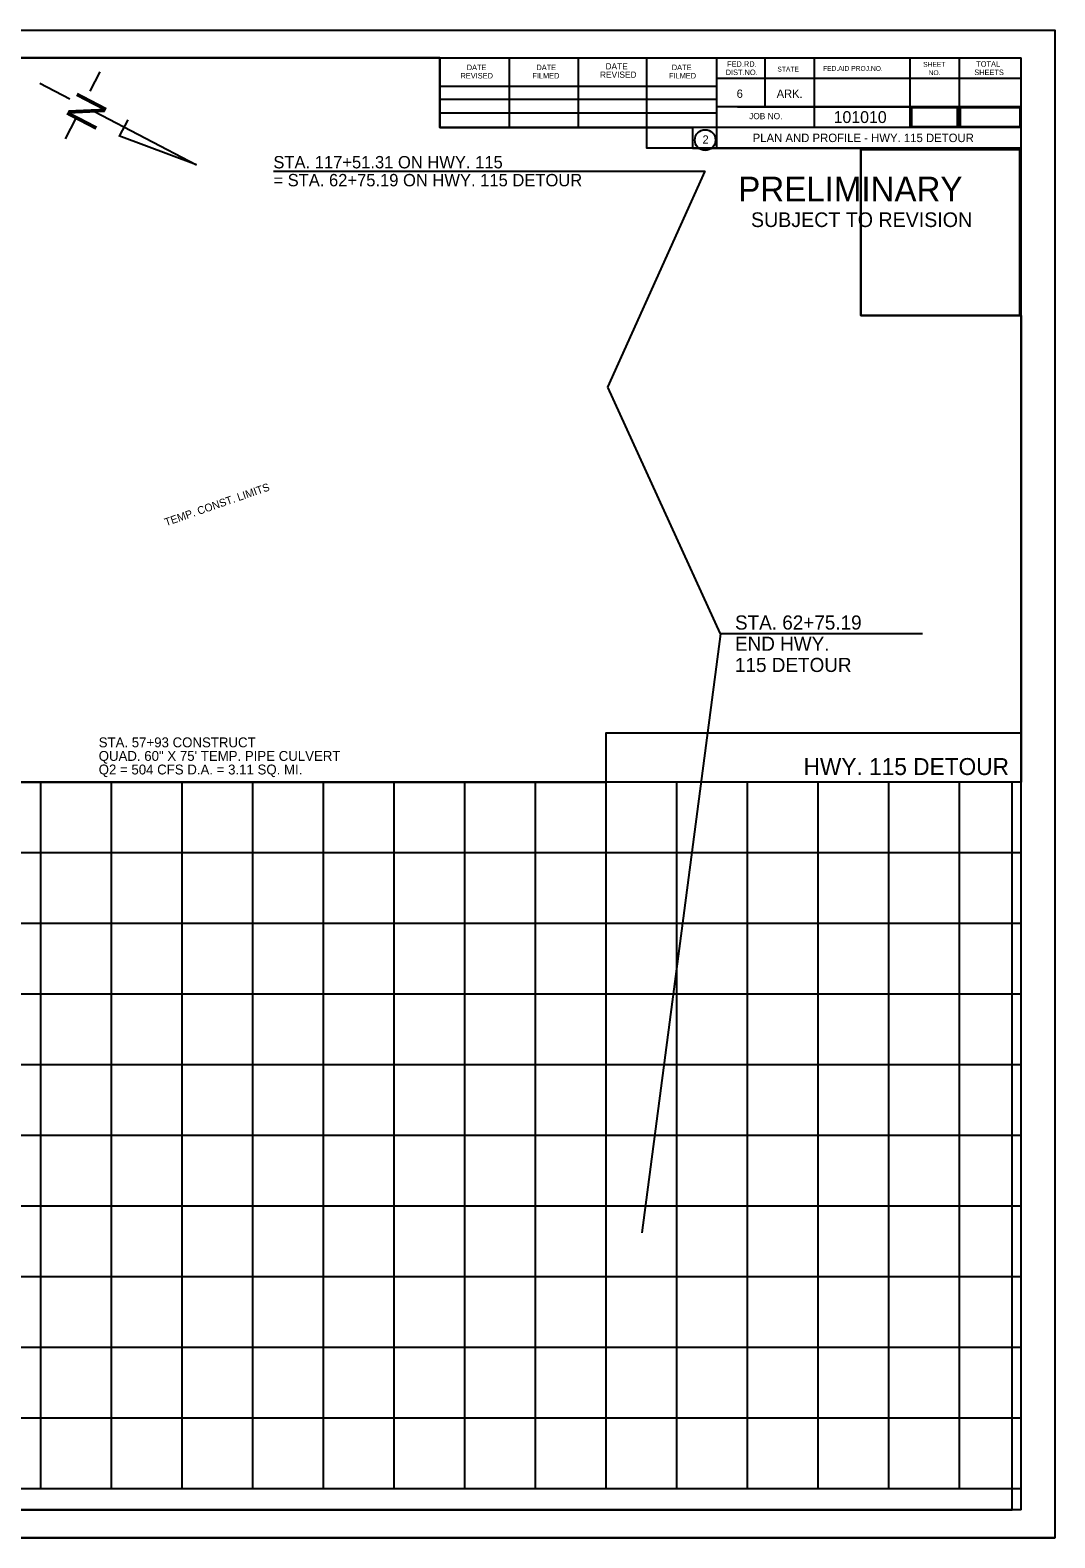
# Model space of a CAD drawing. Extents: x 9887 to 11605, y 9980 to 11268.
# Drawn here: x 10880 to 11605, y 9980 to 11047 of the extents above; entities that cross this region are included whole.
import ezdxf

# ---------------------------------------------------------------- set-up
doc = ezdxf.new("R2010")
doc.units = 0
for name, color, linetype in [('DATE', 7, 'Continuous'), ('GREEN_TXT', 7, 'Continuous'), ('Page Number', 7, 'Continuous'), ('R_Alg Annot', 7, 'Continuous'), ('R_Border Notes', 7, 'Continuous'), ('R_Border PE', 7, 'Continuous'), ('R_No Plot', 7, 'Continuous'), ('R_Proposed Const Limits Annot', 7, 'Continuous'), ('RC Box Annot', 7, 'Continuous'), ('SEAL-INFO', 7, 'Continuous'), ('SIGNATURE', 7, 'Continuous'), ('Total_Pages', 7, 'Continuous')]:
    doc.layers.add(name, color=color, linetype=linetype)

msp = doc.modelspace()

# ---------------------------------------------------------------- linework, layer by layer
for p, q in [((10886.6, 11009.4), (10907.8, 10998.3)), ((10929.1, 11017.4), (10922, 11003.7)), ((10925.3, 10989.2), (10997.4, 10951.6)), ((10912, 10984.5), (10904.4, 10969.9)), ((10948.8, 10983.3), (10942.8, 10971.8)), ((10997.4, 10951.6), (10942.4, 10972))]:
    msp.add_line(p, q)
at = {"layer": 'DATE'}
msp.add_line((11368.1, 10619.6), (11312.5, 10195.9), dxfattribs=at)
msp.add_lwpolyline([(11511.1, 10619.6), (11368.1, 10619.6), (11288.4, 10794.3)], dxfattribs=at)
at = {"layer": 'GREEN_TXT'}
for p, q in [((10000, 11027.3), (11580.9, 11027.3)), ((11169.6, 10977.9), (11169.6, 11027.3)), ((11218.9, 10977.9), (11218.9, 11026.3)), ((11267.7, 10977.9), (11267.7, 11026.3)), ((11316.1, 10977.9), (11316.1, 11026.3)), ((11365.4, 11027.3), (11365.4, 10963.3)), ((11399.6, 11027.3), (11399.6, 10992.6)), ((11434.3, 11027.3), (11434.3, 10977.9)), ((11502.2, 11027.3), (11502.2, 10977.9)), ((11536.9, 11027.3), (11536.9, 10977.9)), ((11580.9, 10000), (11580.9, 11027.3)), ((11580.9, 11012.6), (11365.4, 11012.6)), ((11580.9, 11012.7), (11580.9, 11012.7)), ((11169.6, 11007.2), (11365.4, 11007.2)), ((11169.6, 10997.9), (11365.4, 10997.9)), ((11169.6, 10977.9), (11169.6, 10988.2)), ((11169.6, 10988.2), (11365.4, 10988.2)), ((11580.9, 10992.6), (11365.4, 10992.6)), ((11380.2, 10992.6), (11580.9, 10992.6)), ((11580.9, 10977.9), (11169.6, 10977.9)), ((11365.4, 10963.3), (11580.9, 10963.3)), ((11580.9, 10514.7), (10000, 10514.7)), ((10887.3, 10014.7), (10887.3, 10514.7)), ((10937.3, 10014.7), (10937.3, 10514.7)), ((10987.3, 10014.7), (10987.3, 10514.7)), ((11037.3, 10014.7), (11037.3, 10514.7)), ((11087.3, 10014.7), (11087.3, 10514.7)), ((11137.3, 10014.7), (11137.3, 10514.7)), ((11187.3, 10014.7), (11187.3, 10514.7)), ((11237.3, 10014.7), (11237.3, 10514.7)), ((11287.3, 10014.7), (11287.3, 10514.7)), ((11337.3, 10014.7), (11337.3, 10514.7)), ((11387.3, 10014.7), (11387.3, 10514.7)), ((11437.3, 10014.7), (11437.3, 10514.7)), ((11487.3, 10014.7), (11487.3, 10514.7)), ((11537.3, 10014.7), (11537.3, 10514.7)), ((11580.9, 10464.7), (10000, 10464.7)), ((11580.9, 10414.7), (10000, 10414.7)), ((11580.9, 10364.7), (10000, 10364.7)), ((11580.9, 10314.7), (10000, 10314.7)), ((11580.9, 10264.7), (10000, 10264.7)), ((11580.9, 10214.7), (10000, 10214.7)), ((11580.9, 10164.7), (10000, 10164.7)), ((11580.9, 10114.7), (10000, 10114.7)), ((11580.9, 10064.7), (10000, 10064.7)), ((11580.9, 10014.7), (10000, 10014.7)), ((11580.9, 10000), (10000, 10000))]:
    msp.add_line(p, q, dxfattribs=at)
msp.add_circle((11357.3, 10969), 7.33, dxfattribs=at)
at = {"layer": 'Page Number'}
msp.add_lwpolyline([(11503.2, 10978.6), (11535.9, 10978.6), (11535.9, 10991.9), (11503.2, 10991.9)], close=True, dxfattribs=at)
at = {"layer": 'R_Alg Annot'}
msp.add_line((11051.8, 10947), (11357.4, 10947), dxfattribs=at)
msp.add_lwpolyline([(11288.4, 10794.3), (11357.4, 10947)], dxfattribs=at)
at = {"layer": 'R_No Plot'}
for p, q in [((9938, 11046.8), (11604.7, 11046.8)), ((9938, 9980.1), (11604.7, 9980.1))]:
    msp.add_line(p, q, dxfattribs=at)
for points in [[(9938, 11046.8), (11604.7, 11046.8), (11604.7, 9980.1), (9938, 9980.1)], [(11169.6, 11027.3), (11169.6, 10977.9), (11348.3, 10977.9), (11348.3, 10963.3), (11467.4, 10963.3), (11467.4, 10844.9), (11580.9, 10844.9), (11580.9, 10514.7), (10000, 10514.7), (10000, 11027.3)], [(11467.4, 10962.4), (11579.8, 10962.4), (11579.8, 10844.9), (11467.4, 10844.9)]]:
    msp.add_lwpolyline(points, close=True, dxfattribs=at)
at = {"layer": 'SEAL-INFO'}
for points in [[(10000, 10514.7), (11287.3, 10514.7), (11287.3, 10549.7), (11580.9, 10549.7), (11580.9, 10963.3), (11316.1, 10963.3), (11316.1, 10977.9), (11169.6, 10977.9), (11169.6, 11027.3), (10000, 11027.3)], [(10000, 10514.7), (11287.3, 10514.7), (11287.3, 10549.7), (11580.9, 10549.7), (11580.9, 10963.3), (11316.1, 10963.3), (11316.1, 10977.9), (11169.6, 10977.9), (11169.6, 11027.3), (10000, 11027.3)], [(10000, 10000), (11574.6, 10000), (11574.6, 10514.7), (10000, 10514.7)]]:
    msp.add_lwpolyline(points, close=True, dxfattribs=at)
at = {"layer": 'Total_Pages'}
msp.add_lwpolyline([(11537.7, 10978.6), (11580.1, 10978.6), (11580.1, 10991.9), (11537.7, 10991.9)], close=True, dxfattribs=at)

# ---------------------------------------------------------------- texts
msp.add_text('N', height=23.3, rotation=242.4659).set_placement((10914.5, 11004.8))
msp.add_text('HWY. 115 DETOUR', height=12).set_placement((11426.9, 10519.8))
at = {"layer": 'DATE'}
for s, p in [('STA. 62+75.19', (11378.4, 10622.7)), ('END HWY.', (11378.4, 10607.7)), ('115 DETOUR', (11378.4, 10592.7))]:
    msp.add_text(s, height=10, dxfattribs=at).set_placement(p)
at = {"layer": 'GREEN_TXT'}
for s, height, p in [('DATE', 3.91, (11188.6, 11018.5)), ('DATE', 3.91, (11237.9, 11018.5)), ('DATE', 4.4, (11286.8, 11019)), ('DATE', 3.91, (11333.7, 11018.5)), ('DIST.NO.', 3.91, (11371.8, 11015)), ('FED.RD.', 3.91, (11372.8, 11020.9)), ('STATE', 3.42, (11408.4, 11017.5)), ('FED.AID PROJ.NO.', 3.42, (11440.7, 11018)), ('SHEET', 3.42, (11511.5, 11020.9)), ('SHEETS', 3.91, (11547.7, 11015)), ('TOTAL', 3.91, (11549.1, 11020.9)), ('REVISED', 3.91, (11184.2, 11012.6)), ('FILMED', 3.91, (11235, 11012.6)), ('REVISED', 4.4, (11282.9, 11013.1)), ('FILMED', 3.91, (11331.7, 11012.6)), ('NO.', 3.42, (11515.4, 11015)), ('6', 5.86, (11379.6, 10998.9)), ('ARK.', 5.86, (11407.9, 10998.9)), ('JOB NO.', 4.4, (11388.4, 10983.8)), ('2', 5.86, (11355.4, 10966.5))]:
    msp.add_text(s, height=height, rotation=360, dxfattribs=at).set_placement(p)
at = {"layer": 'R_Alg Annot'}
for s, p in [('STA. 117+51.31 ON HWY. 115', (11051.8, 10949)), ('= STA. 62+75.19 ON HWY. 115 DETOUR', (11051.8, 10936.3))]:
    msp.add_text(s, height=8.75, dxfattribs=at).set_placement(p)
at = {"layer": 'R_Border Notes'}
msp.add_text('101010', height=8.4, dxfattribs=at).set_placement((11448.2, 10981.1))
msp.add_text('PLAN AND PROFILE - HWY. 115 DETOUR', height=6, rotation=360, dxfattribs=at).set_placement((11390.9, 10967.6))
at = {"layer": 'R_Border PE'}
for p in [(11512.5, 10924.4), (11520.8, 10924.5), (11529.6, 10924.4), (11512.4, 10886.6), (11520.8, 10886.6), (11529.6, 10886.5)]:
    msp.add_text('DWB', height=0.1, rotation=360, dxfattribs=at).set_placement(p)
at = {"layer": 'R_Proposed Const Limits Annot'}
msp.add_text('TEMP. CONST. LIMITS', height=5.5, rotation=19.0748, dxfattribs=at).set_placement((10975.9, 10695.8))
at = {"layer": 'RC Box Annot'}
for s, p in [('STA. 57+93 CONSTRUCT', (10928.2, 10539.4)), ('QUAD. 60" X 75\' TEMP. PIPE CULVERT', (10928.2, 10529.8)), ('Q2 = 504 CFS D.A. = 3.11 SQ. MI.', (10928.2, 10520.2))]:
    msp.add_text(s, height=7, dxfattribs=at).set_placement(p)
at = {"layer": 'SIGNATURE'}
for s, height, p in [('PRELIMINARY', 17.5, (11380.7, 10925.6)), ('DWB', 0.1, (11384.4, 10934.9)), ('SUBJECT TO REVISION', 10.376, (11389.7, 10907.5))]:
    msp.add_text(s, height=height, rotation=360, dxfattribs=at).set_placement(p)

doc.saveas('drawing.dxf')
